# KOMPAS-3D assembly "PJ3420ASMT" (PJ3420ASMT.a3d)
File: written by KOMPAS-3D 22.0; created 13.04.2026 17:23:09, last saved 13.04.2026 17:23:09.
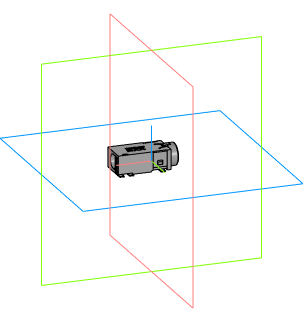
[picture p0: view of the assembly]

Document properties: Автор: Andrey; Полное имя файла: C:\Users\User1\Documents\PJ3420ASMT.a3d

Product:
- Component [detail]: PJ-3420-A-SMT  | qty 1  | source file: PJ-3420-A-SMT.m3d
- Part/product: PJ3420ASMT
    Комментарий: PJ3420ASMT

Referenced files in C:\Users\User1\Documents\: PJ-3420-A-SMT.m3d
